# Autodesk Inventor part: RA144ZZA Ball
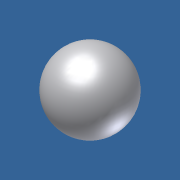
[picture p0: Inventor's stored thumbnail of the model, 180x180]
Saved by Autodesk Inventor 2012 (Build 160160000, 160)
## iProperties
Category: PARTsolutions
Created: 2011-07
Part Number: RA144ZZA Ball
Catalog Web Link: www.cadenas.de
Description: Six types b - Inch system sizes
Document SubType Name: Modeling
Designer: PARTsolutions
Density: 1 g/cm^3
Material: Par défaut
NB: RA144ZZA Ball
NN: Six types b
NT: Inch system sizes
NBSYN: RA144ZZA Ball
LINA: RA144ZZA Ball
SD: 3.175
D: 6.350
B: 2.380
B1: 2.779
D1: 7.52
D2: 7.52
C1: 0.58
C2: 0.79
R: 0.08
ORDER: RA144ZZA
CR: 284
COR: 96
CRF: 29
CORF: 10
LSG: 59000
LSO: 70000
MASS: 0.27
ORDER1: R144
WSS: RA144ZA
WDS: RA144ZZA
UTWF: FLR144
FORSS: FLRA144ZA
FORDS: FLRA144ZZA
DA1: 3.9
DA2: 4
DA: 5.5
RAS: 0.08
MASS1: 0.33
VERS: 3
X: 1.587
N: 9
O: 14.954
RB: 0.470
KT: DUMMY
SUPPLIER: NTN
ARTICLENO: RA144ZZA Ball
BOMINFO: RA144ZZA Ball
CREATOR: CADENAS GmbH
PSOL_IDENT_0: {\\10.0.0.251\ps_data\23d-libs\ntn\ball_roller_bearings\miniature_extra_small_bb\inch_system_sizes\i
PSOL_IDENT_1: ss_ball.prj},176 {VTYP=3D},{NB=RA144ZZA Ball},{LINA=RA144ZZA Ball},{NN=Six types b},{DATE=11.12.2007
PSOL_IDENT_2: 08:48:22},{GEOMDATE=08.02.2007 08:30:00},{VERSION=},{LINEID=16080},{LINESUBID=-1},{WBVAR=}  {NB=RA1
PSOL_IDENT_3: 44ZZA Ball},{LINA=RA144ZZA Ball},{KT=DUMMY},{IDNR=},{SD=3.175},{D=6.350},{B=2.380},{B1=2.779},{D1=7.
PSOL_IDENT_4: 52},{D2=7.52},{C1=0.58},{C2=0.79},{R=0.08},{ORDER=RA144ZZA},{CR=284},{COR=96},{CRF=29},{CORF=10},{LS
PSOL_IDENT_5: G=59000},{LSO=70000},{MASS=0.27},{ORDER1=R144},{WSS=RA144ZA},{WDS=RA144ZZA},{UTWF=FLR144},{FORSS=FLR
PSOL_IDENT_6: A144ZA},{FORDS=FLRA144ZZA},{DA1=3.9},{DA2=4},{DA=5.5},{RAS=0.08},{MASS1=0.33},{VERS=3},{X=1.5875},{N
PSOL_IDENT_7: =9},{O=14.95425},{RB=0.4699}
Title: RA144ZZA Ball
Author: Cadenas PARTsolutions
Comments: Inch system sizes
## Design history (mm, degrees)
sketch "Sketch_1"
  geometry: L1 (0.47, 0)-(-0.47, 0); L2 (0.47, 0)-(-0.47, 0); A1 r 0.47 centre (0, 0) between (0.47, 0) and (-0.47, 0)
  constraints: 4 end point, 2 point on circle, 1 centre point
revolve "Revolution1" sketch "Sketch_1" stored, may be unused: angle "d0" = 360 deg
node "iss_ball_XY"
node "iss_ball_YZ"
node "iss_ball_ZX"
node "iss_ball_X"
node "iss_ball_Y"
node "iss_ball_Z"
node "iss_ball_Center"
node "Solide1"
node "Corps solides"
node "Corps surfaciques"
